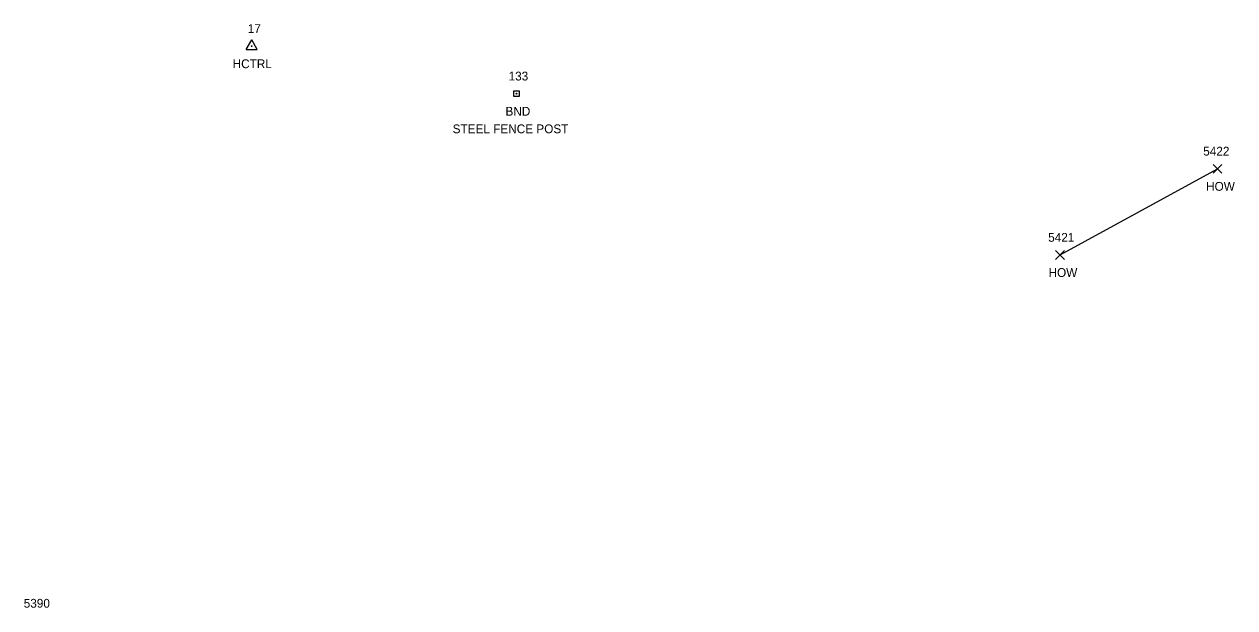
# Model space of a CAD drawing. Extents: x 1481523 to 1489083, y 884156 to 893756.
# Drawn here: x 1487495.3 to 1487770.4, y 886806.3 to 886939 of the extents above; entities that cross this region are included whole.
import ezdxf

# ---------------------------------------------------------------- set-up
doc = ezdxf.new("R2010")
doc.units = 0
for name, color, linetype in [('C_A', 7, 'Continuous'), ('C_I', 7, 'Continuous'), ('CPH', 7, 'Continuous'), ('L_A', 7, 'Continuous'), ('L_I', 7, 'Continuous'), ('L_TIC', 7, 'Continuous'), ('LBC', 7, 'Continuous'), ('Level 18', 7, 'Continuous'), ('M_A', 7, 'Continuous'), ('M_C', 7, 'Continuous'), ('M_I', 7, 'Continuous'), ('R_I', 7, 'Continuous')]:
    doc.layers.add(name, color=color, linetype=linetype)

msp = doc.modelspace()

# ---------------------------------------------------------------- linework, layer by layer
at = {"layer": 'CPH'}
for p, q in [((1487545.75, 886933.33), (1487547, 886935.49)), ((1487548.25, 886933.33), (1487547, 886935.49)), ((1487545.75, 886933.33), (1487548.25, 886933.33)), ((1487547, 886934.05), (1487547, 886934.05))]:
    msp.add_line(p, q, dxfattribs=at)
msp.add_circle((1487547, 886934.05), 0.0833, dxfattribs=at)
at = {"layer": 'L_TIC'}
for points in [[(1487765.49, 886905.17), (1487767.49, 886907.17)], [(1487767.49, 886905.17), (1487765.49, 886907.17)], [(1487729.69, 886885.57), (1487731.69, 886887.57)], [(1487731.69, 886885.57), (1487729.69, 886887.57)]]:
    msp.add_lwpolyline(points, dxfattribs=at)
at = {"layer": 'LBC'}
msp.add_lwpolyline([(1487730.69, 886886.57), (1487766.49, 886906.17)], dxfattribs=at)
at = {"layer": 'Level 18'}
msp.add_lwpolyline([(1487606.55, 886923.88), (1487607.8, 886923.88), (1487607.8, 886922.63), (1487606.55, 886922.63)], close=True, dxfattribs=at)
msp.add_circle((1487607.18, 886923.25), 0.0833, dxfattribs=at)

# ---------------------------------------------------------------- texts
at = {"layer": 'C_A'}
msp.add_text('HCTRL', height=2, dxfattribs=at).set_placement((1487542.67, 886929.05))
at = {"layer": 'C_I'}
msp.add_text('17', height=2, dxfattribs=at).set_placement((1487546.1, 886937.05))
at = {"layer": 'L_A'}
for p in [(1487763.88, 886901.17), (1487728.08, 886881.57)]:
    msp.add_text('HOW', height=2, dxfattribs=at).set_placement(p)
at = {"layer": 'L_I'}
for s, p in [('5422', (1487763.23, 886909.17)), ('5421', (1487728, 886889.57))]:
    msp.add_text(s, height=2, dxfattribs=at).set_placement(p)
at = {"layer": 'M_A'}
msp.add_text('BND', height=2, dxfattribs=at).set_placement((1487604.67, 886918.25))
at = {"layer": 'M_C'}
msp.add_text('STEEL FENCE POST', height=2, dxfattribs=at).set_placement((1487592.67, 886914.25))
at = {"layer": 'M_I'}
msp.add_text('133', height=2, dxfattribs=at).set_placement((1487605.38, 886926.25))
at = {"layer": 'R_I'}
msp.add_text('5390', height=2, dxfattribs=at).set_placement((1487495.2, 886806.36))

doc.saveas('drawing.dxf')
